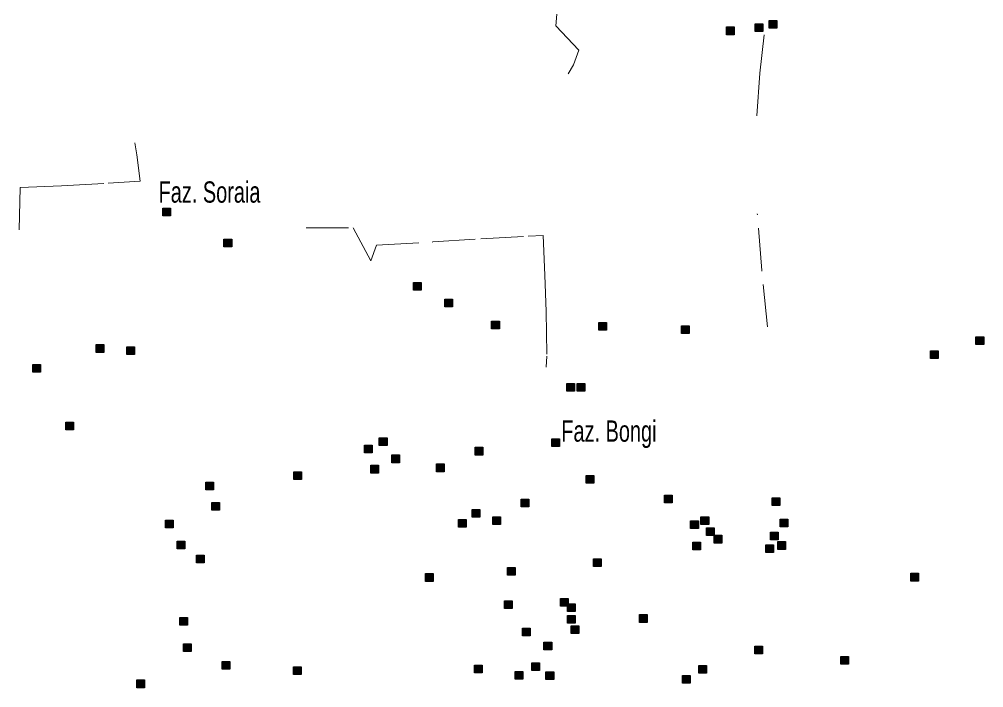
# Model space of a CAD drawing. Extents: x 445.6 to 500, y 8618.1 to 8673.4.
# Drawn here: x 458.01 to 465.26, y 8650.67 to 8655.7 of the extents above; entities that cross this region are included whole.
import ezdxf

# ---------------------------------------------------------------- set-up
doc = ezdxf.new("R2010")
doc.units = 0
doc.header["$LTSCALE"] = 0.064
doc.linetypes.add('DOT_DASHED', pattern=[7.7, 5, -1.2, 0.3, -1.2])
doc.layers.add('2', color=7, linetype='Continuous', lineweight=25)
doc.layers.add('22', color=7, linetype='DOT_DASHED', lineweight=13)
doc.layers.add('61', color=7, linetype='Continuous')

msp = doc.modelspace()

# ---------------------------------------------------------------- hatches: boundary and pattern name
at = {"layer": '2'}
for points in [[(463.3236, 8655.6386), (463.3816, 8655.6386), (463.3816, 8655.5806), (463.3236, 8655.5806)], [(463.5384, 8655.6626), (463.5964, 8655.6626), (463.5964, 8655.6046), (463.5384, 8655.6046)], [(463.6441, 8655.6865), (463.7021, 8655.6865), (463.7021, 8655.6285), (463.6441, 8655.6285)], [(459.0844, 8654.277), (459.1424, 8654.277), (459.1424, 8654.219), (459.0844, 8654.219)], [(459.5448, 8654.0443), (459.6028, 8654.0443), (459.6028, 8653.9863), (459.5448, 8653.9863)], [(460.9695, 8653.7178), (461.0275, 8653.7178), (461.0275, 8653.6598), (460.9695, 8653.6598)], [(461.206, 8653.5924), (461.264, 8653.5924), (461.264, 8653.5344), (461.206, 8653.5344)], [(461.5573, 8653.4264), (461.6153, 8653.4264), (461.6153, 8653.3684), (461.5573, 8653.3684)], [(462.3632, 8653.416), (462.4212, 8653.416), (462.4212, 8653.358), (462.3632, 8653.358)], [(462.9848, 8653.3923), (463.0428, 8653.3923), (463.0428, 8653.3343), (462.9848, 8653.3343)], [(458.5842, 8653.2502), (458.6422, 8653.2502), (458.6422, 8653.1922), (458.5842, 8653.1922)], [(465.1989, 8653.3085), (465.2569, 8653.3085), (465.2569, 8653.2505), (465.1989, 8653.2505)], [(458.8138, 8653.2333), (458.8718, 8653.2333), (458.8718, 8653.1753), (458.8138, 8653.1753)], [(464.8577, 8653.2035), (464.9157, 8653.2035), (464.9157, 8653.1455), (464.8577, 8653.1455)], [(458.1079, 8653.1011), (458.1659, 8653.1011), (458.1659, 8653.0431), (458.1079, 8653.0431)], [(462.1234, 8652.9586), (462.1814, 8652.9586), (462.1814, 8652.9006), (462.1234, 8652.9006)], [(462.2011, 8652.9586), (462.2591, 8652.9586), (462.2591, 8652.9006), (462.2011, 8652.9006)], [(458.3545, 8652.6675), (458.4125, 8652.6675), (458.4125, 8652.6095), (458.3545, 8652.6095)], [(460.7128, 8652.5496), (460.7708, 8652.5496), (460.7708, 8652.4916), (460.7128, 8652.4916)], [(462.0086, 8652.5419), (462.0666, 8652.5419), (462.0666, 8652.4839), (462.0086, 8652.4839)], [(460.6013, 8652.4954), (460.6593, 8652.4954), (460.6593, 8652.4374), (460.6013, 8652.4374)], [(461.4322, 8652.4784), (461.4902, 8652.4784), (461.4902, 8652.4204), (461.4322, 8652.4204)], [(460.8073, 8652.4208), (460.8653, 8652.4208), (460.8653, 8652.3628), (460.8073, 8652.3628)], [(460.6486, 8652.3429), (460.7066, 8652.3429), (460.7066, 8652.2849), (460.6486, 8652.2849)], [(461.1417, 8652.3531), (461.1997, 8652.3531), (461.1997, 8652.2951), (461.1417, 8652.2951)], [(460.07, 8652.2945), (460.128, 8652.2945), (460.128, 8652.2365), (460.07, 8652.2365)], [(462.2687, 8652.2674), (462.3267, 8652.2674), (462.3267, 8652.2094), (462.2687, 8652.2094)], [(459.4079, 8652.217), (459.4659, 8652.217), (459.4659, 8652.159), (459.4079, 8652.159)], [(461.7785, 8652.0876), (461.8365, 8652.0876), (461.8365, 8652.0296), (461.7785, 8652.0296)], [(462.8564, 8652.1184), (462.9144, 8652.1184), (462.9144, 8652.0604), (462.8564, 8652.0604)], [(463.6653, 8652.099), (463.7233, 8652.099), (463.7233, 8652.041), (463.6653, 8652.041)], [(459.4527, 8652.0639), (459.5107, 8652.0639), (459.5107, 8652.0059), (459.4527, 8652.0059)], [(461.411, 8652.0104), (461.469, 8652.0104), (461.469, 8651.9524), (461.411, 8651.9524)], [(461.5656, 8651.9555), (461.6236, 8651.9555), (461.6236, 8651.8975), (461.5656, 8651.8975)], [(463.1312, 8651.9556), (463.1892, 8651.9556), (463.1892, 8651.8976), (463.1312, 8651.8976)], [(459.1048, 8651.9318), (459.1628, 8651.9318), (459.1628, 8651.8738), (459.1048, 8651.8738)], [(461.3089, 8651.9352), (461.3669, 8651.9352), (461.3669, 8651.8772), (461.3089, 8651.8772)], [(463.0535, 8651.9251), (463.1115, 8651.9251), (463.1115, 8651.8671), (463.0535, 8651.8671)], [(463.1717, 8651.8742), (463.2297, 8651.8742), (463.2297, 8651.8162), (463.1717, 8651.8162)], [(463.7257, 8651.9386), (463.7837, 8651.9386), (463.7837, 8651.8806), (463.7257, 8651.8806)], [(463.2291, 8651.8166), (463.2871, 8651.8166), (463.2871, 8651.7586), (463.2291, 8651.7586)], [(463.6547, 8651.8404), (463.7127, 8651.8404), (463.7127, 8651.7824), (463.6547, 8651.7824)], [(459.1926, 8651.7725), (459.2506, 8651.7725), (459.2506, 8651.7145), (459.1926, 8651.7145)], [(463.0704, 8651.7658), (463.1284, 8651.7658), (463.1284, 8651.7078), (463.0704, 8651.7078)], [(463.6176, 8651.7455), (463.6756, 8651.7455), (463.6756, 8651.6875), (463.6176, 8651.6875)], [(463.7088, 8651.7692), (463.7668, 8651.7692), (463.7668, 8651.7112), (463.7088, 8651.7112)], [(459.3379, 8651.6675), (459.3959, 8651.6675), (459.3959, 8651.6095), (459.3379, 8651.6095)], [(462.3239, 8651.6405), (462.3819, 8651.6405), (462.3819, 8651.5825), (462.3239, 8651.5825)], [(461.059, 8651.5286), (461.117, 8651.5286), (461.117, 8651.4706), (461.059, 8651.4706)], [(461.6771, 8651.576), (461.7351, 8651.576), (461.7351, 8651.518), (461.6771, 8651.518)], [(464.7093, 8651.5309), (464.7673, 8651.5309), (464.7673, 8651.4729), (464.7093, 8651.4729)], [(461.6535, 8651.3253), (461.7115, 8651.3253), (461.7115, 8651.2673), (461.6535, 8651.2673)], [(462.0757, 8651.3423), (462.1337, 8651.3423), (462.1337, 8651.2843), (462.0757, 8651.2843)], [(462.1279, 8651.3017), (462.1859, 8651.3017), (462.1859, 8651.2437), (462.1279, 8651.2437)], [(462.6684, 8651.2204), (462.7264, 8651.2204), (462.7264, 8651.1624), (462.6684, 8651.1624)], [(459.2129, 8651.2), (459.2709, 8651.2), (459.2709, 8651.142), (459.2129, 8651.142)], [(462.1279, 8651.2136), (462.1859, 8651.2136), (462.1859, 8651.1556), (462.1279, 8651.1556)], [(461.7886, 8651.1186), (461.8466, 8651.1186), (461.8466, 8651.0606), (461.7886, 8651.0606)], [(462.155, 8651.1357), (462.213, 8651.1357), (462.213, 8651.0777), (462.155, 8651.0777)], [(459.2399, 8651.0001), (459.2979, 8651.0001), (459.2979, 8650.9421), (459.2399, 8650.9421)], [(461.9507, 8651.0136), (462.0087, 8651.0136), (462.0087, 8650.9556), (461.9507, 8650.9556)], [(463.5365, 8650.9832), (463.5945, 8650.9832), (463.5945, 8650.9252), (463.5365, 8650.9252)], [(459.5304, 8650.8679), (459.5884, 8650.8679), (459.5884, 8650.8099), (459.5304, 8650.8099)], [(461.8595, 8650.8578), (461.9175, 8650.8578), (461.9175, 8650.7998), (461.8595, 8650.7998)], [(464.1827, 8650.9053), (464.2407, 8650.9053), (464.2407, 8650.8473), (464.1827, 8650.8473)], [(460.0675, 8650.8273), (460.1255, 8650.8273), (460.1255, 8650.7693), (460.0675, 8650.7693)], [(461.4272, 8650.8408), (461.4852, 8650.8408), (461.4852, 8650.7828), (461.4272, 8650.7828)], [(461.7345, 8650.7934), (461.7925, 8650.7934), (461.7925, 8650.7354), (461.7345, 8650.7354)], [(461.9658, 8650.7901), (462.0238, 8650.7901), (462.0238, 8650.7321), (461.9658, 8650.7321)], [(463.1143, 8650.8375), (463.1723, 8650.8375), (463.1723, 8650.7795), (463.1143, 8650.7795)], [(458.8901, 8650.729), (458.9481, 8650.729), (458.9481, 8650.671), (458.8901, 8650.671)], [(462.9927, 8650.763), (463.0507, 8650.763), (463.0507, 8650.705), (462.9927, 8650.705)]]:
    msp.add_hatch(color=256, dxfattribs=at).paths.add_polyline_path(points)

# ---------------------------------------------------------------- linework, layer by layer
for points in [[(463.3236, 8655.6386), (463.3816, 8655.6386), (463.3816, 8655.5806), (463.3236, 8655.5806)], [(463.5384, 8655.6626), (463.5964, 8655.6626), (463.5964, 8655.6046), (463.5384, 8655.6046)], [(463.6441, 8655.6865), (463.7021, 8655.6865), (463.7021, 8655.6285), (463.6441, 8655.6285)], [(459.0844, 8654.277), (459.1424, 8654.277), (459.1424, 8654.219), (459.0844, 8654.219)], [(459.5448, 8654.0443), (459.6028, 8654.0443), (459.6028, 8653.9863), (459.5448, 8653.9863)], [(460.9695, 8653.7178), (461.0275, 8653.7178), (461.0275, 8653.6598), (460.9695, 8653.6598)], [(461.206, 8653.5924), (461.264, 8653.5924), (461.264, 8653.5344), (461.206, 8653.5344)], [(461.5573, 8653.4264), (461.6153, 8653.4264), (461.6153, 8653.3684), (461.5573, 8653.3684)], [(462.3632, 8653.416), (462.4212, 8653.416), (462.4212, 8653.358), (462.3632, 8653.358)], [(462.9848, 8653.3923), (463.0428, 8653.3923), (463.0428, 8653.3343), (462.9848, 8653.3343)], [(458.5842, 8653.2502), (458.6422, 8653.2502), (458.6422, 8653.1922), (458.5842, 8653.1922)], [(465.1989, 8653.3085), (465.2569, 8653.3085), (465.2569, 8653.2505), (465.1989, 8653.2505)], [(458.8138, 8653.2333), (458.8718, 8653.2333), (458.8718, 8653.1753), (458.8138, 8653.1753)], [(464.8577, 8653.2035), (464.9157, 8653.2035), (464.9157, 8653.1455), (464.8577, 8653.1455)], [(458.1079, 8653.1011), (458.1659, 8653.1011), (458.1659, 8653.0431), (458.1079, 8653.0431)], [(462.1234, 8652.9586), (462.1814, 8652.9586), (462.1814, 8652.9006), (462.1234, 8652.9006)], [(462.2011, 8652.9586), (462.2591, 8652.9586), (462.2591, 8652.9006), (462.2011, 8652.9006)], [(458.3545, 8652.6675), (458.4125, 8652.6675), (458.4125, 8652.6095), (458.3545, 8652.6095)], [(460.7128, 8652.5496), (460.7708, 8652.5496), (460.7708, 8652.4916), (460.7128, 8652.4916)], [(462.0086, 8652.5419), (462.0666, 8652.5419), (462.0666, 8652.4839), (462.0086, 8652.4839)], [(460.6013, 8652.4954), (460.6593, 8652.4954), (460.6593, 8652.4374), (460.6013, 8652.4374)], [(461.4322, 8652.4784), (461.4902, 8652.4784), (461.4902, 8652.4204), (461.4322, 8652.4204)], [(460.8073, 8652.4208), (460.8653, 8652.4208), (460.8653, 8652.3628), (460.8073, 8652.3628)], [(460.6486, 8652.3429), (460.7066, 8652.3429), (460.7066, 8652.2849), (460.6486, 8652.2849)], [(461.1417, 8652.3531), (461.1997, 8652.3531), (461.1997, 8652.2951), (461.1417, 8652.2951)], [(460.07, 8652.2945), (460.128, 8652.2945), (460.128, 8652.2365), (460.07, 8652.2365)], [(462.2687, 8652.2674), (462.3267, 8652.2674), (462.3267, 8652.2094), (462.2687, 8652.2094)], [(459.4079, 8652.217), (459.4659, 8652.217), (459.4659, 8652.159), (459.4079, 8652.159)], [(461.7785, 8652.0876), (461.8365, 8652.0876), (461.8365, 8652.0296), (461.7785, 8652.0296)], [(462.8564, 8652.1184), (462.9144, 8652.1184), (462.9144, 8652.0604), (462.8564, 8652.0604)], [(463.6653, 8652.099), (463.7233, 8652.099), (463.7233, 8652.041), (463.6653, 8652.041)], [(459.4527, 8652.0639), (459.5107, 8652.0639), (459.5107, 8652.0059), (459.4527, 8652.0059)], [(461.411, 8652.0104), (461.469, 8652.0104), (461.469, 8651.9524), (461.411, 8651.9524)], [(461.5656, 8651.9555), (461.6236, 8651.9555), (461.6236, 8651.8975), (461.5656, 8651.8975)], [(463.1312, 8651.9556), (463.1892, 8651.9556), (463.1892, 8651.8976), (463.1312, 8651.8976)], [(459.1048, 8651.9318), (459.1628, 8651.9318), (459.1628, 8651.8738), (459.1048, 8651.8738)], [(461.3089, 8651.9352), (461.3669, 8651.9352), (461.3669, 8651.8772), (461.3089, 8651.8772)], [(463.0535, 8651.9251), (463.1115, 8651.9251), (463.1115, 8651.8671), (463.0535, 8651.8671)], [(463.1717, 8651.8742), (463.2297, 8651.8742), (463.2297, 8651.8162), (463.1717, 8651.8162)], [(463.7257, 8651.9386), (463.7837, 8651.9386), (463.7837, 8651.8806), (463.7257, 8651.8806)], [(463.2291, 8651.8166), (463.2871, 8651.8166), (463.2871, 8651.7586), (463.2291, 8651.7586)], [(463.6547, 8651.8404), (463.7127, 8651.8404), (463.7127, 8651.7824), (463.6547, 8651.7824)], [(459.1926, 8651.7725), (459.2506, 8651.7725), (459.2506, 8651.7145), (459.1926, 8651.7145)], [(463.0704, 8651.7658), (463.1284, 8651.7658), (463.1284, 8651.7078), (463.0704, 8651.7078)], [(463.6176, 8651.7455), (463.6756, 8651.7455), (463.6756, 8651.6875), (463.6176, 8651.6875)], [(463.7088, 8651.7692), (463.7668, 8651.7692), (463.7668, 8651.7112), (463.7088, 8651.7112)], [(459.3379, 8651.6675), (459.3959, 8651.6675), (459.3959, 8651.6095), (459.3379, 8651.6095)], [(462.3239, 8651.6405), (462.3819, 8651.6405), (462.3819, 8651.5825), (462.3239, 8651.5825)], [(461.059, 8651.5286), (461.117, 8651.5286), (461.117, 8651.4706), (461.059, 8651.4706)], [(461.6771, 8651.576), (461.7351, 8651.576), (461.7351, 8651.518), (461.6771, 8651.518)], [(464.7093, 8651.5309), (464.7673, 8651.5309), (464.7673, 8651.4729), (464.7093, 8651.4729)], [(461.6535, 8651.3253), (461.7115, 8651.3253), (461.7115, 8651.2673), (461.6535, 8651.2673)], [(462.0757, 8651.3423), (462.1337, 8651.3423), (462.1337, 8651.2843), (462.0757, 8651.2843)], [(462.1279, 8651.3017), (462.1859, 8651.3017), (462.1859, 8651.2437), (462.1279, 8651.2437)], [(462.6684, 8651.2204), (462.7264, 8651.2204), (462.7264, 8651.1624), (462.6684, 8651.1624)], [(459.2129, 8651.2), (459.2709, 8651.2), (459.2709, 8651.142), (459.2129, 8651.142)], [(462.1279, 8651.2136), (462.1859, 8651.2136), (462.1859, 8651.1556), (462.1279, 8651.1556)], [(461.7886, 8651.1186), (461.8466, 8651.1186), (461.8466, 8651.0606), (461.7886, 8651.0606)], [(462.155, 8651.1357), (462.213, 8651.1357), (462.213, 8651.0777), (462.155, 8651.0777)], [(459.2399, 8651.0001), (459.2979, 8651.0001), (459.2979, 8650.9421), (459.2399, 8650.9421)], [(461.9507, 8651.0136), (462.0087, 8651.0136), (462.0087, 8650.9556), (461.9507, 8650.9556)], [(463.5365, 8650.9832), (463.5945, 8650.9832), (463.5945, 8650.9252), (463.5365, 8650.9252)], [(459.5304, 8650.8679), (459.5884, 8650.8679), (459.5884, 8650.8099), (459.5304, 8650.8099)], [(461.8595, 8650.8578), (461.9175, 8650.8578), (461.9175, 8650.7998), (461.8595, 8650.7998)], [(464.1827, 8650.9053), (464.2407, 8650.9053), (464.2407, 8650.8473), (464.1827, 8650.8473)], [(460.0675, 8650.8273), (460.1255, 8650.8273), (460.1255, 8650.7693), (460.0675, 8650.7693)], [(461.4272, 8650.8408), (461.4852, 8650.8408), (461.4852, 8650.7828), (461.4272, 8650.7828)], [(461.7345, 8650.7934), (461.7925, 8650.7934), (461.7925, 8650.7354), (461.7345, 8650.7354)], [(461.9658, 8650.7901), (462.0238, 8650.7901), (462.0238, 8650.7321), (461.9658, 8650.7321)], [(463.1143, 8650.8375), (463.1723, 8650.8375), (463.1723, 8650.7795), (463.1143, 8650.7795)], [(458.8901, 8650.729), (458.9481, 8650.729), (458.9481, 8650.671), (458.8901, 8650.671)], [(462.9927, 8650.763), (463.0507, 8650.763), (463.0507, 8650.705), (462.9927, 8650.705)]]:
    msp.add_lwpolyline(points, close=True, dxfattribs=at)
at = {"layer": '22'}
for points in [[(462.0926, 8656.1522), (462.0395, 8655.6478), (462.2134, 8655.4652), (462.1733, 8655.3538), (462.1322, 8655.2865)], [(463.6062, 8655.5805), (463.5725, 8655.2906), (463.5484, 8654.909)], [(458.0058, 8654.1132), (458.0124, 8654.4317), (458.3229, 8654.445), (458.6731, 8654.4635), (458.9145, 8654.4794), (458.8906, 8654.6781), (458.8756, 8654.7669)], [(463.6311, 8653.3835), (463.5886, 8653.8066), (463.5543, 8654.233)], [(460.162, 8654.1279), (460.5168, 8654.1277), (460.6493, 8653.8807), (460.6905, 8653.9983), (461.1145, 8654.0219), (461.4766, 8654.0454), (461.8329, 8654.066), (461.9447, 8654.0718), (461.9565, 8653.7719), (461.9668, 8653.4994), (461.9727, 8653.1642), (461.9684, 8653.0815)]]:
    msp.add_lwpolyline(points, dxfattribs=at)

# ---------------------------------------------------------------- texts
at = {"layer": '61', "width": 0.7}
for s, p in [('Faz. Soraia', (459.0531, 8654.3175)), ('Faz. Bongi', (462.081, 8652.5206))]:
    msp.add_text(s, height=0.16, dxfattribs=at).set_placement(p)

doc.saveas('drawing.dxf')
